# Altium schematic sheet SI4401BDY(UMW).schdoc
size 127 x 101 mm
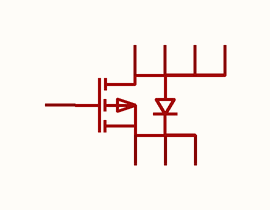
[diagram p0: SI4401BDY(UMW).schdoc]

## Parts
Q?  si4401bdy(umw)  [SOIC-8_L4.9-W3.9-P1.27-LS6.2-BL]  (value not drawn)

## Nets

Not connected (* = marked no-connect by the designer): Q? 1(S) 2(S) 3(S) 4(G) 5(D) 6(D) 7(D) 8(D)

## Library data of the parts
Q? = si4401bdy(umw): 数量:1个P沟道;漏源电压(Vdss):40V;连续漏极电流(Id):16.1A;导通电阻(RDS(on)):18mΩ@10V；29mΩ@4.5V;耗散功率(Pd):6.3W;阈值电压(Vgs(th)):2.5V;; Manufacturer: UMW(友台半导体); AddInBom: yes; ModelId: 23a59470b1e946e0afe388c2a9d3f488; ModelTransform: 192.913,236.22,0,0,0,0,0,0,0; Number: 1个P沟道; Drain to Source Voltage: 40V; Current - Continuous Drain(Id): 16.1A; Pd - Power Dissipation: 6.3W; Gate Threshold Voltage (Vgs(th)): 2.5V; Gate Charge(Qg): 64nC@10V；33nC@4.5V; Input Capacitance(Ciss): 3.007nF; Reverse Transfer Capacitance (Crss@Vds): 291pF; Output Capacitance(Coss): 335pF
